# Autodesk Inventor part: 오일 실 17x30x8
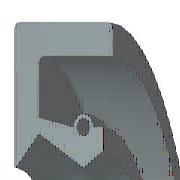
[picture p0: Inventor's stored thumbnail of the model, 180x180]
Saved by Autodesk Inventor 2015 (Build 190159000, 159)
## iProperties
IsCustomPart: 1
Created: 2012-02
Part Number: 오일 실 17x30x8
Material: 고무
Description: 오일-실
Document SubType Name: Modeling
Standard: KS B 2804
Designer: mduedu
Standards Organization: KS
Language: ko-KR
Size Designation: D - 17 30 8
Categories: <MemberInstance><Categories><Category DisplayName="샤프트 부품" InternalName="7f7aeb1f-a693-4053-b835-cee3144e0d98" Mnemonic="SHFT"><Category DisplayName="실링" Intern
Density: 0.93 g/cm^3
Appearance: 고무 - 검은색 - 버전 1.1
Author: mduedu
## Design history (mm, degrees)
revolve "본체" stored, may be unused: angle "d17" = 90 deg
revolve "스프링1" stored, may be unused: angle "d18" = 90 deg
body "Solid1"
sketch "스케치1"
  geometry: L1 (0, 15)-(8, 15); L2 (8, 13.25)-(1.75, 13.25); L3 (1.75, 10.25)-(4.9, 8.5); L4 (4.9, 8.5)-(0, 8.5); L5 (0, 0)-(9.586, 0) reference; L6 (4.9, 8.5)-(6.3, 9.375); L7 (0, 18)-(0, -3) reference; L8 (-1.941, 0)-(11.507, 0) reference; L9 (4.2, 10.6)-(1.75, 11.21); L10 (1.75, 11.21)-(1.75, 13.25); L11 (0, 15)-(0, 8.588); L12 (4.9, 8.5)-(0, 8.5); L13 (1.75, 10.25)-(0.152, 8.528); L14 (8, 15)-(8, 13.25); L15 (5.6, 10.6)-(6.3, 10.6); L16 (6.3, 10.6)-(6.3, 9.375); C1 r 0.455 at (4.9, 10.6); A1 r 0.7 centre (4.9, 10.6) between (5.6, 10.6) and (4.2, 10.6); A2 r 0.088 centre (0.088, 8.588) between (0, 8.588) and (0.152, 8.528); 1 further point
  constraints: 28 end point, 5 horizontal alignment, 5 point on line, 4 point on circle, 4 vertical alignment, 3 centre point, 3 tangent, 2 collinear, 2 horizontal, 2 perpendicular, 1 coincident, 1 parallel
  dimensions: "d0" = 30 diameter of L1 L5 (= SD2); "d1" = 1.75 distance of L1.end L2.start (= SD); "d2" = 0.91 diameter of C1 (= SPDI); "d3" = 1.4 diameter of A1 (= SPDA); "d4" = 17 diameter of L3.end L5 (= NND); "d5" = 20.5 diameter of L3.start L5 (= TKDM); "d7" = 22.42 diameter of L9.end L5 (= TKDM + 0.24 x SWDT); "d8" = 1.75 distance between parallel lines of L11 L10 (= SD); "d9" = 4.9 distance from line of L11 C1.centre (= SPDST); "d10" = 21.2 diameter of C1.centre L5 (= HLDM); "d11" = 0.0875 radius of A2 (= 0.25 x LAB); "d12" = 6.3 distance between parallel lines of L11 L16 (= SDI); "d13" = 18.75 diameter of L6.end L5 (= ABDM); "d14" = 8 distance from line of L11 L1.end (= SWDT)
fillet "모깎기1" dims "d6" = 0.3 (= RR)
other parameters: "SD2" = 30 [user parameter; used in 1 equation term], "SWDT" = 8 [user parameter; used in 2 equation terms], "RR" = 0.3 [user parameter; used in 1 equation term], "SD" = 1.75 [user parameter; used in 2 equation terms], "NND" = 17 [user parameter; used in 1 equation term], "SPDA" = 1.4 [user parameter; used in 1 equation term], "SPDI" = 0.91 [user parameter; used in 1 equation term], "TKDM" = 20.5 [user parameter; used in 2 equation terms], "HLDM" = 21.2 [user parameter; used in 1 equation term], "ABDM" = 18.75 [user parameter; used in 1 equation term], "SDI" = 6.3 [user parameter; used in 1 equation term], "SPDST" = 4.9 [user parameter; used in 1 equation term], "LAB" = 0.35 [user parameter; used in 1 equation term], "d15" = 0, "d16" = 0, "d19" = 0
